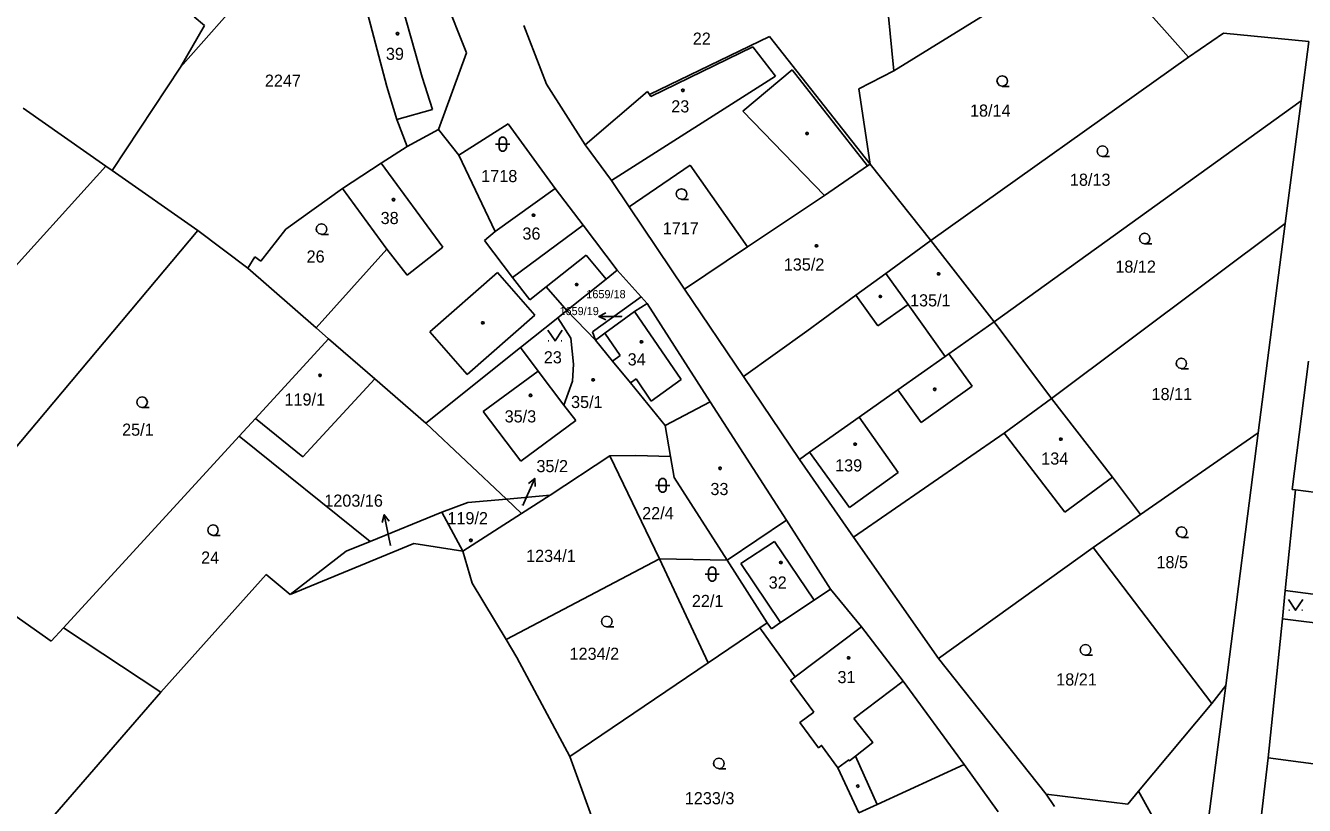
# Model space of a CAD drawing. Extents: x -802857 to -799647, y -1020285 to -1015884.
# Drawn here: x -801501.8 to -801322.5, y -1017885.2 to -1017775.9 of the extents above; entities that cross this region are included whole.
import ezdxf

# ---------------------------------------------------------------- set-up
doc = ezdxf.new("R2010")
doc.units = 0
for name, color, linetype in [('Default', 7, 'Continuous'), ('KN_HRANICE', 7, 'Continuous'), ('KN_KULTURY', 7, 'Continuous'), ('KN_PARCELY', 7, 'Continuous'), ('KN_SLUCKY', 7, 'Continuous')]:
    doc.layers.add(name, color=color, linetype=linetype)

# ---------------------------------------------------------------- blocks, each defined once
blk = doc.blocks.new('304')
at = {"layer": 'Default'}
blk.add_lwpolyline([(0, 0), (-0.38, 0.1), (-0.65, 0.37), (-0.75, 0.74), (-0.65, 1.11), (-0.38, 1.38), (-0.01, 1.48), (0.36, 1.38), (0.63, 1.11), (0.73, 0.73), (0.63, 0.35), (0.36, 0.08), (-0.02, -0.02), (0.98, -0.02)], dxfattribs=at)
blk = doc.blocks.new('314')
at = {"layer": 'Default'}
for p, q in [((-0.95, 0), (-0.85, 0)), ((0.85, 0), (0.95, 0))]:
    blk.add_line(p, q, dxfattribs=at)
blk.add_lwpolyline([(-1, 1.5), (0, 0), (1, 1.5)], dxfattribs=at)
blk = doc.blocks.new('316')
at = {"layer": 'Default'}
for points in [[(-0.5, 1.5), (-0.4, 1.79), (-0.15, 1.97), (0.16, 1.97), (0.41, 1.79), (0.51, 1.5), (0.51, 0.5), (0.41, 0.21), (0.16, 0.03), (-0.15, 0.03), (-0.4, 0.21), (-0.5, 0.5), (-0.5, 1.5)], [(-1, 1), (0.27, 1), (1, 1)]]:
    blk.add_lwpolyline(points, dxfattribs=at)
blk = doc.blocks.new('NAHRADNI_SYMBOL')
at = {"layer": 'Default'}
blk.add_lwpolyline([(0.09, 0.15), (0.18, 0), (0.09, -0.15), (-0.09, -0.15), (-0.18, 0), (-0.09, 0.15), (0.09, 0.15)], dxfattribs=at)
blk = doc.blocks.new('10292')
at = {"layer": 'Default'}
blk.add_line((0, 3), (0, 0), dxfattribs=at)
blk.add_lwpolyline([(-0.5, 2), (0, 3), (0.5, 2)], dxfattribs=at)
blk = doc.blocks.new('402')
at = {"layer": 'Default'}
blk.add_lwpolyline([(0.09, 0.15), (0.18, 0), (0.09, -0.15), (-0.09, -0.15), (-0.18, 0), (-0.09, 0.15), (0.09, 0.15)], dxfattribs=at)

msp = doc.modelspace()

# ---------------------------------------------------------------- linework, layer by layer
at = {"layer": 'KN_HRANICE'}
for p, q in [((-801338.75, -1017780.31), (-801349.19, -1017768.52)), ((-801443.81, -1017770.05), (-801439.99, -1017779.67)), ((-801454.34, -1017772.35), (-801451.15, -1017784.39)), ((-801478.17, -1017774.62), (-801476.71, -1017775.88)), ((-801380.06, -1017782.2), (-801380.85, -1017774.15)), ((-801367.27, -1017774.31), (-801380.06, -1017782.2)), ((-801476.71, -1017775.88), (-801480.11, -1017781.68)), ((-801428.76, -1017784.1), (-801431.94, -1017775.86)), ((-801397.51, -1017777.38), (-801414.33, -1017785.51)), ((-801383.41, -1017795.28), (-801397.51, -1017777.38)), ((-801333.83, -1017776.95), (-801338.75, -1017780.31)), ((-801321.89, -1017778.08), (-801333.83, -1017776.95)), ((-801321.89, -1017778.08), (-801322.97, -1017786.42)), ((-801439.99, -1017779.67), (-801443.92, -1017790.45)), ((-801480.11, -1017781.68), (-801489.69, -1017796.18)), ((-801374.87, -1017805.99), (-801338.75, -1017780.31)), ((-801384.96, -1017784.74), (-801380.06, -1017782.2)), ((-801449.74, -1017789.03), (-801451.15, -1017784.39)), ((-801423.33, -1017792.57), (-801428.76, -1017784.1)), ((-801423.33, -1017792.57), (-801414.6, -1017785.1)), ((-801414.6, -1017785.1), (-801414.33, -1017785.51)), ((-801383.41, -1017795.28), (-801384.96, -1017784.74)), ((-801502.15, -1017787.45), (-801490.56, -1017795.57)), ((-801365.98, -1017817.41), (-801322.97, -1017786.42)), ((-801322.97, -1017786.42), (-801325.18, -1017803.59)), ((-801448.33, -1017792.81), (-801449.74, -1017789.03)), ((-801443.92, -1017790.45), (-801448.33, -1017792.81)), ((-801441.05, -1017794.03), (-801443.92, -1017790.45)), ((-801434.16, -1017789.65), (-801441.05, -1017794.03)), ((-801427.55, -1017798.69), (-801434.16, -1017789.65)), ((-801448.33, -1017792.81), (-801451.95, -1017795.16)), ((-801419.68, -1017797.56), (-801423.33, -1017792.57)), ((-801441.05, -1017794.03), (-801435.97, -1017804.71)), ((-801531.17, -1017840.39), (-801490.56, -1017795.57)), ((-801490.56, -1017795.57), (-801489.69, -1017796.18)), ((-801489.69, -1017796.18), (-801477.67, -1017804.6)), ((-801451.95, -1017795.16), (-801457.4, -1017798.7)), ((-801408.62, -1017795.44), (-801417.17, -1017801.29)), ((-801400.57, -1017806.9), (-801408.62, -1017795.44)), ((-801389.8, -1017799.67), (-801383.76, -1017795.52)), ((-801383.76, -1017795.52), (-801383.41, -1017795.28)), ((-801374.87, -1017805.99), (-801383.41, -1017795.28)), ((-801417.17, -1017801.29), (-801419.68, -1017797.56)), ((-801457.4, -1017798.7), (-801465.32, -1017804.39)), ((-801457.4, -1017798.7), (-801451.18, -1017807.22)), ((-801435.97, -1017804.71), (-801427.55, -1017798.69)), ((-801427.55, -1017798.69), (-801423.63, -1017803.84)), ((-801389.8, -1017799.67), (-801400.57, -1017806.9)), ((-801409.4, -1017812.82), (-801417.17, -1017801.29)), ((-801357.94, -1017828.12), (-801325.18, -1017803.59)), ((-801325.18, -1017803.59), (-801328.97, -1017832.94)), ((-801477.67, -1017804.6), (-801504.93, -1017837.07)), ((-801477.67, -1017804.6), (-801470.67, -1017809.89)), ((-801468.83, -1017808.88), (-801465.32, -1017804.39)), ((-801437.48, -1017806.01), (-801435.97, -1017804.71)), ((-801418.85, -1017810.16), (-801423.63, -1017803.84)), ((-801437.48, -1017806.01), (-801433.56, -1017811.16)), ((-801400.57, -1017806.9), (-801409.4, -1017812.82)), ((-801374.87, -1017805.99), (-801381.18, -1017810.6)), ((-801365.98, -1017817.41), (-801374.87, -1017805.99)), ((-801470.67, -1017809.89), (-801469.67, -1017808.26)), ((-801469.67, -1017808.26), (-801468.83, -1017808.88)), ((-801451.18, -1017807.22), (-801461.07, -1017818.23)), ((-801461.07, -1017818.23), (-801470.67, -1017809.89)), ((-801420.41, -1017811.41), (-801418.85, -1017810.16)), ((-801415.49, -1017813.9), (-801418.85, -1017810.16)), ((-801381.18, -1017810.6), (-801385.38, -1017813.66)), ((-801433.56, -1017811.16), (-801431.13, -1017814.33)), ((-801431.13, -1017814.33), (-801428.82, -1017812.49)), ((-801428.82, -1017812.49), (-801425.91, -1017815.81)), ((-801425.91, -1017815.81), (-801420.41, -1017811.41)), ((-801415.49, -1017813.9), (-801422.32, -1017818.81)), ((-801414.68, -1017814.8), (-801415.49, -1017813.9)), ((-801401.17, -1017825.03), (-801409.4, -1017812.82)), ((-801392.29, -1017818.71), (-801385.38, -1017813.66)), ((-801425.91, -1017815.81), (-801427.16, -1017816.81)), ((-801421.92, -1017819.94), (-801425.91, -1017815.81)), ((-801416.42, -1017815.95), (-801420.6, -1017818.97)), ((-801414.68, -1017814.8), (-801416.42, -1017815.95)), ((-801414.68, -1017814.8), (-801405.8, -1017828.59)), ((-801427.16, -1017816.81), (-801432.4, -1017820.99)), ((-801427.16, -1017816.81), (-801425.38, -1017819.7)), ((-801372.35, -1017821.89), (-801365.98, -1017817.41)), ((-801357.94, -1017828.12), (-801365.98, -1017817.41)), ((-801469.57, -1017830.92), (-801459.32, -1017819.75)), ((-801459.32, -1017819.75), (-801461.07, -1017818.23)), ((-801452.84, -1017825.38), (-801459.32, -1017819.75)), ((-801425.38, -1017819.7), (-801424.98, -1017823.33)), ((-801422.32, -1017818.81), (-801421.92, -1017819.94)), ((-801420.6, -1017818.97), (-801421.92, -1017819.94)), ((-801392.29, -1017818.71), (-801401.17, -1017825.03)), ((-801432.4, -1017820.99), (-801445.69, -1017831.57)), ((-801429.94, -1017824.32), (-801432.4, -1017820.99)), ((-801419.5, -1017822.9), (-801421.92, -1017819.94)), ((-801424.98, -1017823.33), (-801425.14, -1017825.72)), ((-801417.01, -1017825.94), (-801419.5, -1017822.9)), ((-801379.5, -1017826.93), (-801372.88, -1017822.26)), ((-801372.88, -1017822.26), (-801372.35, -1017821.89)), ((-801324.21, -1017840.9), (-801321.92, -1017822.92)), ((-801429.94, -1017824.32), (-801437.65, -1017829.98)), ((-801426.33, -1017829.07), (-801429.94, -1017824.32)), ((-801393.31, -1017836.69), (-801401.17, -1017825.03)), ((-801445.69, -1017831.57), (-801452.84, -1017825.38)), ((-801425.14, -1017825.72), (-801426.33, -1017829.07)), ((-801412.13, -1017831.91), (-801417.01, -1017825.94)), ((-801412.13, -1017831.91), (-801405.8, -1017828.59)), ((-801395.11, -1017845.2), (-801405.8, -1017828.59)), ((-801384.94, -1017830.76), (-801379.5, -1017826.93)), ((-801357.94, -1017828.12), (-801364.61, -1017832.99)), ((-801357.94, -1017828.12), (-801349.4, -1017839.18)), ((-801437.65, -1017829.98), (-801432.37, -1017836.91)), ((-801424.68, -1017831.24), (-801426.33, -1017829.07)), ((-801471.87, -1017833.43), (-801469.57, -1017830.92)), ((-801445.69, -1017831.57), (-801434.4, -1017842.23)), ((-801432.37, -1017836.91), (-801424.68, -1017831.24)), ((-801412.13, -1017831.91), (-801411.38, -1017836.27)), ((-801391.89, -1017835.66), (-801384.94, -1017830.76)), ((-801496.49, -1017860.26), (-801471.87, -1017833.43)), ((-801471.87, -1017833.43), (-801453.5, -1017848.16)), ((-801364.61, -1017832.99), (-801385.73, -1017847.55)), ((-801328.97, -1017832.94), (-801345.47, -1017844.4)), ((-801328.97, -1017832.94), (-801333.53, -1017868.36)), ((-801393.31, -1017836.69), (-801391.89, -1017835.66)), ((-801428.24, -1017841.68), (-801419.87, -1017836.18)), ((-801419.87, -1017836.18), (-801416.24, -1017836.14)), ((-801419.87, -1017836.18), (-801412.93, -1017850.63)), ((-801416.24, -1017836.14), (-801411.38, -1017836.27)), ((-801411.38, -1017836.27), (-801410.87, -1017839.19)), ((-801385.73, -1017847.55), (-801393.31, -1017836.69)), ((-801403.45, -1017850.81), (-801410.87, -1017839.19)), ((-801349.4, -1017839.18), (-801345.47, -1017844.4)), ((-801325.19, -1017855.03), (-801323.76, -1017840.95)), ((-801324.21, -1017840.9), (-801323.76, -1017840.95)), ((-801323.76, -1017840.95), (-801319.39, -1017841.48)), ((-801443.47, -1017844.07), (-801439.8, -1017842.71)), ((-801439.8, -1017842.71), (-801434.4, -1017842.23)), ((-801434.4, -1017842.23), (-801428.24, -1017841.68)), ((-801434.4, -1017842.23), (-801432.26, -1017844.25)), ((-801432.26, -1017844.25), (-801428.24, -1017841.68)), ((-801453.5, -1017848.16), (-801443.47, -1017844.07)), ((-801440.51, -1017849.54), (-801443.47, -1017844.07)), ((-801440.51, -1017849.54), (-801432.26, -1017844.25)), ((-801345.47, -1017844.4), (-801352.14, -1017849.02)), ((-801395.11, -1017845.2), (-801403.45, -1017850.81)), ((-801395.11, -1017845.2), (-801388.93, -1017854.84)), ((-801456.88, -1017849.54), (-801453.5, -1017848.16)), ((-801373.83, -1017864.59), (-801385.73, -1017847.55)), ((-801464.7, -1017855.62), (-801447.38, -1017848.46)), ((-801464.7, -1017855.62), (-801456.88, -1017849.54)), ((-801447.38, -1017848.46), (-801440.51, -1017849.54)), ((-801440.51, -1017849.54), (-801439.2, -1017854.03)), ((-801352.14, -1017849.02), (-801373.83, -1017864.59)), ((-801352.14, -1017849.02), (-801335.46, -1017870.88)), ((-801412.93, -1017850.63), (-801434.44, -1017861.93)), ((-801412.93, -1017850.63), (-801406.12, -1017865.17)), ((-801412.93, -1017850.63), (-801403.45, -1017850.81)), ((-801397.85, -1017859.59), (-801403.45, -1017850.81)), ((-801510.41, -1017853.59), (-801498.22, -1017862.16)), ((-801468.1, -1017852.81), (-801482.86, -1017869.28)), ((-801464.7, -1017855.62), (-801468.1, -1017852.81)), ((-801434.44, -1017861.93), (-801439.2, -1017854.03)), ((-801388.93, -1017854.84), (-801391.24, -1017856.42)), ((-801388.93, -1017854.84), (-801384.62, -1017860.12)), ((-801325.59, -1017859.01), (-801325.19, -1017855.03)), ((-801325.19, -1017855.03), (-801307.53, -1017857.34)), ((-801391.24, -1017856.42), (-801395.94, -1017859.52)), ((-801327.56, -1017878.51), (-801325.59, -1017859.01)), ((-801325.59, -1017859.01), (-801307.91, -1017861.25)), ((-801498.22, -1017862.16), (-801496.49, -1017860.26)), ((-801496.49, -1017860.26), (-801482.86, -1017869.28)), ((-801406.12, -1017865.17), (-801398.86, -1017860.27)), ((-801398.86, -1017860.27), (-801397.85, -1017859.59)), ((-801398.86, -1017860.27), (-801393.89, -1017867.15)), ((-801397.85, -1017859.59), (-801397.24, -1017860.42)), ((-801395.94, -1017859.52), (-801397.24, -1017860.42)), ((-801384.62, -1017860.12), (-801378.78, -1017867.74)), ((-801432.94, -1017864.42), (-801434.44, -1017861.93)), ((-801432.94, -1017864.42), (-801425.5, -1017878.33)), ((-801425.5, -1017878.33), (-801406.12, -1017865.17)), ((-801373.83, -1017864.59), (-801358.71, -1017883.58)), ((-801393.89, -1017867.15), (-801394.58, -1017867.67)), ((-801394.58, -1017867.67), (-801391.31, -1017872.09)), ((-801378.78, -1017867.74), (-801370.22, -1017879.44)), ((-801514.75, -1017906.05), (-801482.86, -1017869.28)), ((-801333.53, -1017868.36), (-801336.82, -1017893.87)), ((-801335.46, -1017870.88), (-801333.53, -1017868.36)), ((-801345.75, -1017883.16), (-801335.46, -1017870.88)), ((-801414.45, -1017908.61), (-801425.5, -1017878.33)), ((-801327.56, -1017878.51), (-801330.54, -1017903.51)), ((-801252.11, -1017888.65), (-801327.56, -1017878.51)), ((-801387.94, -1017879.91), (-801384.99, -1017886.23)), ((-801370.22, -1017879.44), (-801365.46, -1017886.06)), ((-801347.28, -1017884.99), (-801358.71, -1017883.58)), ((-801358.71, -1017883.58), (-801357.53, -1017885.3)), ((-801347.28, -1017884.99), (-801345.75, -1017883.16))]:
    msp.add_line(p, q, dxfattribs=at)
for points in [[(-801480.11, -1017781.68), (-801470.32, -1017770.64), (-801461.06, -1017763.9), (-801461.81, -1017762.88), (-801451.46, -1017755.42)], [(-801391.31, -1017872.09), (-801393.23, -1017873.56), (-801390.62, -1017877.09), (-801390.19, -1017876.77), (-801387.94, -1017879.91)]]:
    msp.add_lwpolyline(points, dxfattribs=at)
at = {"layer": 'KN_PARCELY'}
for p, q in [((-801418.23, -1017816.65), (-801418.45, -1017816.65)), ((-801432.09, -1017843.12), (-801431.63, -1017842.08)), ((-801450.64, -1017848.75), (-801450.92, -1017847.38))]:
    msp.add_line(p, q, dxfattribs=at)
at = {"layer": 'KN_SLUCKY'}
for p, q in [((-801446.22, -1017783.09), (-801449.49, -1017771.37)), ((-801414.14, -1017785.81), (-801399.82, -1017778.87)), ((-801399.82, -1017778.87), (-801396.67, -1017782.95)), ((-801394.31, -1017782.09), (-801401.22, -1017787.85)), ((-801394.31, -1017782.09), (-801383.76, -1017795.52)), ((-801446.22, -1017783.09), (-801444.76, -1017787.62)), ((-801396.67, -1017782.95), (-801419.68, -1017797.56)), ((-801414.33, -1017785.51), (-801414.14, -1017785.81)), ((-801444.76, -1017787.62), (-801449.74, -1017789.03)), ((-801401.22, -1017787.85), (-801389.8, -1017799.67)), ((-801443.31, -1017806.94), (-801451.95, -1017795.16)), ((-801423.63, -1017803.84), (-801433.56, -1017811.16)), ((-801443.31, -1017806.94), (-801448.29, -1017810.84)), ((-801448.29, -1017810.84), (-801451.18, -1017807.22)), ((-801428.82, -1017812.49), (-801423.23, -1017808.03)), ((-801423.23, -1017808.03), (-801420.41, -1017811.41)), ((-801435.66, -1017810.47), (-801445.14, -1017818.79)), ((-801435.66, -1017810.47), (-801430.41, -1017816.45)), ((-801378.08, -1017814.96), (-801381.18, -1017810.6)), ((-801382.33, -1017817.95), (-801385.38, -1017813.66)), ((-801416.42, -1017815.95), (-801409.91, -1017825.48)), ((-801378.08, -1017814.96), (-801382.33, -1017817.95)), ((-801372.88, -1017822.26), (-801378.08, -1017814.96)), ((-801430.41, -1017816.45), (-801439.89, -1017824.77)), ((-801445.14, -1017818.79), (-801439.89, -1017824.77)), ((-801420.6, -1017818.97), (-801418.44, -1017822.13)), ((-801418.44, -1017822.13), (-801419.5, -1017822.9)), ((-801369.08, -1017826.42), (-801372.35, -1017821.89)), ((-801462.96, -1017836.32), (-801452.84, -1017825.38)), ((-801416.2, -1017825.4), (-801417.01, -1017825.94)), ((-801416.2, -1017825.4), (-801414.09, -1017828.5)), ((-801409.91, -1017825.48), (-801414.09, -1017828.5)), ((-801376.26, -1017831.48), (-801369.08, -1017826.42)), ((-801376.26, -1017831.48), (-801379.5, -1017826.93)), ((-801469.57, -1017830.92), (-801462.96, -1017836.32)), ((-801384.94, -1017830.76), (-801379.47, -1017838.53)), ((-801364.61, -1017832.99), (-801356.07, -1017844.05)), ((-801391.89, -1017835.66), (-801386.28, -1017843.41)), ((-801386.28, -1017843.41), (-801379.47, -1017838.53)), ((-801349.4, -1017839.18), (-801356.07, -1017844.05)), ((-801401.52, -1017851.28), (-801396.82, -1017848.18)), ((-801391.24, -1017856.42), (-801396.82, -1017848.18)), ((-801395.94, -1017859.52), (-801401.52, -1017851.28)), ((-801393.89, -1017867.15), (-801384.62, -1017860.12)), ((-801385.7, -1017872.97), (-801378.78, -1017867.74)), ((-801385.45, -1017878.25), (-801382.41, -1017885.03)), ((-801382.41, -1017885.03), (-801370.22, -1017879.44)), ((-801335.32, -1017902), (-801345.75, -1017883.16)), ((-801382.41, -1017885.03), (-801384.99, -1017886.23))]:
    msp.add_line(p, q, dxfattribs=at)
for points in [[(-801385.7, -1017872.97), (-801383.02, -1017876.35), (-801385.45, -1017878.25)], [(-801385.45, -1017878.25), (-801386.29, -1017878.91), (-801386.38, -1017878.8), (-801387.94, -1017879.91)]]:
    msp.add_lwpolyline(points, dxfattribs=at)

# ---------------------------------------------------------------- block references
at = {"layer": 'KN_KULTURY'}
for name, p in [('402', (-801449.66, -1017777)), ('304', (-801364.86, -1017784.37)), ('402', (-801409.65, -1017784.94)), ('402', (-801392.24, -1017791)), ('316', (-801434.91, -1017793.48)), ('304', (-801350.81, -1017794.21)), ('304', (-801409.84, -1017800.21)), ('402', (-801450.22, -1017800.26)), ('402', (-801430.58, -1017802.44)), ('304', (-801460.32, -1017805.12)), ('304', (-801344.89, -1017806.46)), ('NAHRADNI_SYMBOL', (-801390.91, -1017806.74)), ('402', (-801373.79, -1017810.66)), ('402', (-801424.54, -1017812.17)), ('402', (-801381.96, -1017813.83)), ('402', (-801437.71, -1017817.54)), ('314', (-801427.58, -1017820.06)), ('402', (-801415.46, -1017820.19)), ('304', (-801339.75, -1017823.95)), ('402', (-801460.53, -1017824.88)), ('NAHRADNI_SYMBOL', (-801422.23, -1017825.51)), ('402', (-801374.34, -1017826.85)), ('304', (-801485.47, -1017829.39)), ('402', (-801431, -1017827.7)), ('402', (-801356.66, -1017833.84)), ('402', (-801385.49, -1017834.54)), ('316', (-801412.5, -1017841.31)), ('NAHRADNI_SYMBOL', (-801404.44, -1017837.92)), ('304', (-801475.52, -1017847.32)), ('304', (-801339.71, -1017847.59)), ('NAHRADNI_SYMBOL', (-801439.37, -1017848.01)), ('316', (-801405.54, -1017853.75)), ('402', (-801395.91, -1017851.12)), ('314', (-801323.73, -1017857.81)), ('304', (-801420.31, -1017860.13)), ('304', (-801353.19, -1017864.1)), ('402', (-801386.41, -1017864.49)), ('304', (-801404.59, -1017880.01))]:
    msp.add_blockref(name, p, dxfattribs=at)
at = {"layer": 'KN_KULTURY', "rotation": -154.995701}
msp.add_blockref('402', (-801385.13, -1017882.46), dxfattribs=at)
at = {"layer": 'KN_PARCELY'}
for p, rotation in [((-801418.45, -1017816.65), 89.438712), ((-801431.63, -1017842.08), -23.845662), ((-801450.92, -1017847.38), 11.516452)]:
    msp.add_blockref('10292', p, dxfattribs=dict(at, rotation=rotation))

# ---------------------------------------------------------------- texts
for s, height, p in [('22', 1.7, (-801408.26, -1017778.55)), ('39', 1.7, (-801451.29, -1017780.68)), ('2247', 1.7, (-801468.26, -1017784.44)), ('23', 1.7, (-801411.28, -1017788.04)), ('18/14', 1.7, (-801369.39, -1017788.63)), ('1718', 1.7, (-801437.92, -1017797.81)), ('18/13', 1.7, (-801355.38, -1017798.32)), ('38', 1.7, (-801452.03, -1017803.69)), ('1717', 1.7, (-801412.48, -1017805.14)), ('36', 1.7, (-801432.15, -1017805.87)), ('26', 1.7, (-801462.41, -1017809.08)), ('135/2', 1.7, (-801395.5, -1017810.2)), ('18/12', 1.7, (-801349.01, -1017810.5)), ('1659/18', 1.14, (-801423.19, -1017814.08)), ('135/1', 1.7, (-801377.8, -1017815.23)), ('1659/19', 1.14, (-801426.95, -1017816.45)), ('1659/19', 0.1, (-801418.57, -1017816.65)), ('23', 1.7, (-801429.15, -1017823.21)), ('34', 1.7, (-801417.39, -1017823.5)), ('18/11', 1.7, (-801343.93, -1017828.36)), ('119/1', 1.7, (-801465.51, -1017829.12)), ('35/1', 1.7, (-801425.33, -1017829.47)), ('35/3', 1.7, (-801434.64, -1017831.49)), ('25/1', 1.7, (-801488.28, -1017833.35)), ('134', 1.7, (-801359.4, -1017837.4)), ('35/2', 1.7, (-801430.18, -1017838.46)), ('139', 1.7, (-801388.3, -1017838.36)), ('33', 1.7, (-801405.79, -1017841.67)), ('1203/16', 1.7, (-801459.93, -1017843.3)), ('35/2', 0.1, (-801432.29, -1017843.12)), ('119/2', 1.7, (-801442.67, -1017845.76)), ('22/4', 1.7, (-801415.36, -1017845.05)), ('24', 1.7, (-801477.2, -1017851.28)), ('1203/16', 0.1, (-801450.99, -1017848.75)), ('1234/1', 1.7, (-801431.63, -1017851.04)), ('18/5', 1.7, (-801343.25, -1017851.92)), ('32', 1.7, (-801397.62, -1017854.77)), ('22/1', 1.7, (-801408.39, -1017857.36)), ('1234/2', 1.7, (-801425.54, -1017864.76)), ('31', 1.7, (-801387.97, -1017868.03)), ('18/21', 1.7, (-801357.3, -1017868.36)), ('1233/3', 1.7, (-801409.38, -1017885.01))]:
    msp.add_text(s, height=height, dxfattribs=at).set_placement(p)

doc.saveas('drawing.dxf')
